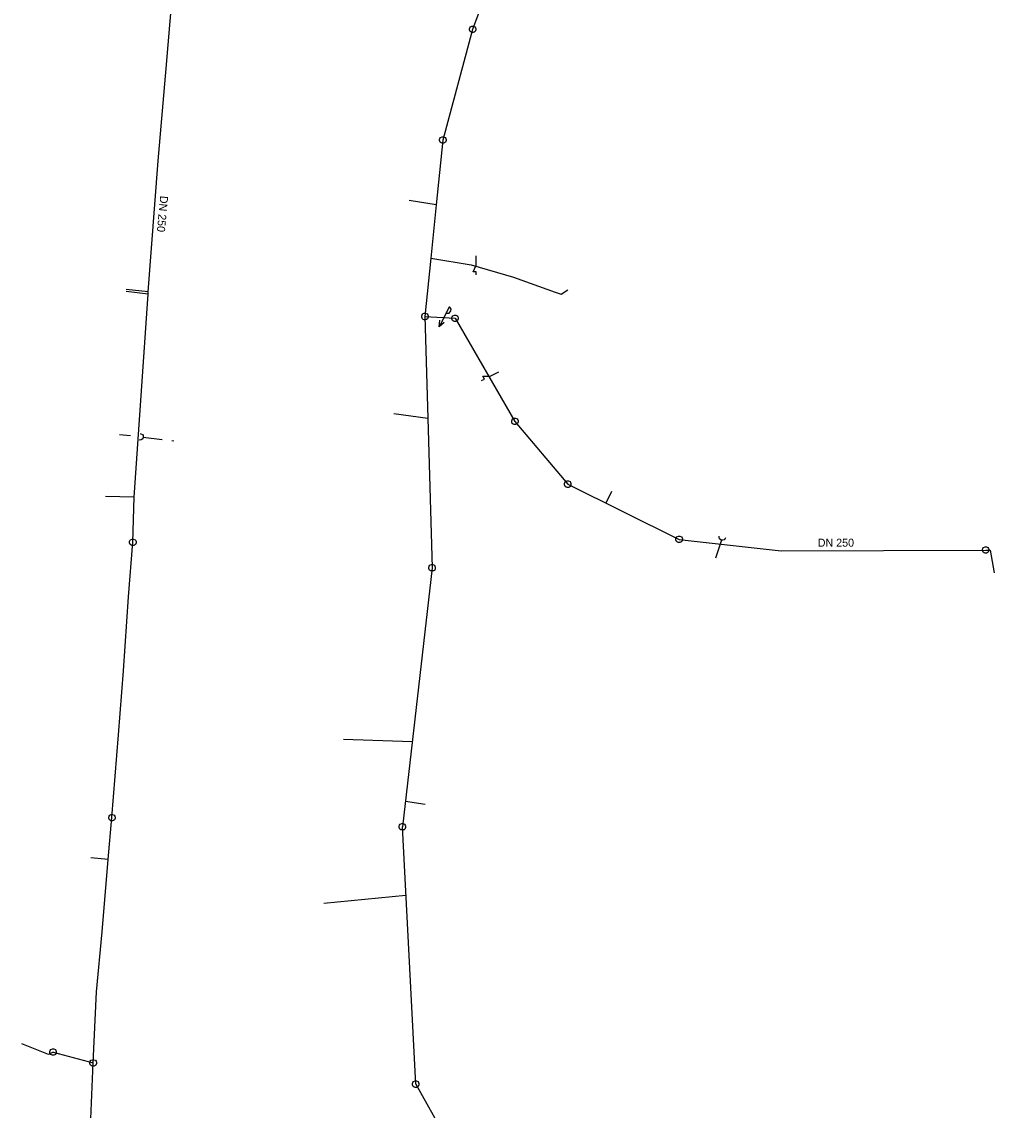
# Model space of a CAD drawing. Extents: x -717256 to -716843, y -1145423 to -1142840.
# Drawn here: x -716994.8 to -716842.9, y -1145075.9 to -1144905.8 of the extents above; entities that cross this region are included whole.
import ezdxf

# ---------------------------------------------------------------- set-up
doc = ezdxf.new("R2010")
doc.units = 0
for name, color, linetype in [('Vrstva 30', 7, 'Continuous'), ('Vrstva 31', 7, 'Continuous'), ('Vrstva 9', 7, 'Continuous')]:
    doc.layers.add(name, color=color, linetype=linetype)

msp = doc.modelspace()

# ---------------------------------------------------------------- linework, layer by layer
at = {"layer": 'Vrstva 30'}
for p, q in [((-716972.263, -1144913.081), (-716969.992, -1144886.715)), ((-716923.436, -1144904.319), (-716924.397, -1144906.971)), ((-716924.747, -1144906.571), (-716924.497, -1144906.471)), ((-716924.497, -1144906.471), (-716924.297, -1144906.471)), ((-716924.297, -1144906.471), (-716924.047, -1144906.571)), ((-716924.397, -1144906.971), (-716929.047, -1144924.264)), ((-716924.897, -1144906.871), (-716924.847, -1144906.721)), ((-716924.897, -1144907.071), (-716924.897, -1144906.871)), ((-716924.797, -1144907.321), (-716924.897, -1144907.071)), ((-716924.847, -1144906.721), (-716924.747, -1144906.571)), ((-716924.647, -1144907.421), (-716924.797, -1144907.321)), ((-716924.497, -1144907.471), (-716924.647, -1144907.421)), ((-716924.297, -1144907.471), (-716924.497, -1144907.471)), ((-716924.147, -1144907.421), (-716924.297, -1144907.471)), ((-716923.997, -1144907.321), (-716924.147, -1144907.421)), ((-716924.047, -1144906.571), (-716923.947, -1144906.721)), ((-716923.897, -1144907.071), (-716923.997, -1144907.321)), ((-716923.947, -1144906.721), (-716923.897, -1144906.871)), ((-716923.897, -1144906.871), (-716923.897, -1144907.071)), ((-716973.504, -1144927.52), (-716972.263, -1144913.081)), ((-716929.047, -1144924.264), (-716930.074, -1144934.378)), ((-716929.547, -1144924.164), (-716929.497, -1144924.014)), ((-716929.547, -1144924.364), (-716929.547, -1144924.164)), ((-716929.447, -1144924.614), (-716929.547, -1144924.364)), ((-716929.497, -1144924.014), (-716929.397, -1144923.864)), ((-716929.297, -1144924.714), (-716929.447, -1144924.614)), ((-716929.397, -1144923.864), (-716929.147, -1144923.764)), ((-716929.147, -1144924.764), (-716929.297, -1144924.714)), ((-716929.147, -1144923.764), (-716928.947, -1144923.764)), ((-716928.947, -1144924.764), (-716929.147, -1144924.764)), ((-716928.947, -1144923.764), (-716928.697, -1144923.864)), ((-716928.797, -1144924.714), (-716928.947, -1144924.764)), ((-716928.647, -1144924.614), (-716928.797, -1144924.714)), ((-716928.697, -1144923.864), (-716928.597, -1144924.014)), ((-716928.547, -1144924.364), (-716928.647, -1144924.614)), ((-716928.597, -1144924.014), (-716928.547, -1144924.164)), ((-716928.547, -1144924.164), (-716928.547, -1144924.364)), ((-716975.088, -1144947.993), (-716973.504, -1144927.52)), ((-716930.074, -1144934.378), (-716930.922, -1144942.731)), ((-716930.922, -1144942.731), (-716931.848, -1144951.843)), ((-716977.25, -1144980.08), (-716975.096, -1144948.367)), ((-716975.096, -1144948.367), (-716975.088, -1144947.993)), ((-716932.348, -1144951.743), (-716932.298, -1144951.593)), ((-716932.348, -1144951.943), (-716932.348, -1144951.743)), ((-716932.248, -1144952.193), (-716932.348, -1144951.943)), ((-716932.298, -1144951.593), (-716932.198, -1144951.443)), ((-716932.098, -1144952.293), (-716932.248, -1144952.193)), ((-716932.198, -1144951.443), (-716931.948, -1144951.343)), ((-716931.948, -1144952.343), (-716932.098, -1144952.293)), ((-716931.948, -1144951.343), (-716931.748, -1144951.343)), ((-716931.748, -1144952.343), (-716931.948, -1144952.343)), ((-716931.848, -1144951.843), (-716927.138, -1144952.119)), ((-716931.848, -1144951.843), (-716931.392, -1144967.726)), ((-716931.748, -1144951.343), (-716931.498, -1144951.443)), ((-716931.598, -1144952.293), (-716931.748, -1144952.343)), ((-716931.448, -1144952.193), (-716931.598, -1144952.293)), ((-716931.498, -1144951.443), (-716931.398, -1144951.593)), ((-716931.348, -1144951.943), (-716931.448, -1144952.193)), ((-716931.398, -1144951.593), (-716931.348, -1144951.743)), ((-716931.348, -1144951.743), (-716931.348, -1144951.943)), ((-716927.638, -1144952.019), (-716927.588, -1144951.869)), ((-716927.638, -1144952.219), (-716927.638, -1144952.019)), ((-716927.538, -1144952.469), (-716927.638, -1144952.219)), ((-716927.588, -1144951.869), (-716927.488, -1144951.719)), ((-716927.488, -1144951.719), (-716927.238, -1144951.619)), ((-716927.238, -1144951.619), (-716927.038, -1144951.619)), ((-716927.138, -1144952.119), (-716917.792, -1144968.219)), ((-716927.038, -1144951.619), (-716926.788, -1144951.719)), ((-716926.788, -1144951.719), (-716926.688, -1144951.869)), ((-716926.638, -1144952.219), (-716926.738, -1144952.469)), ((-716926.688, -1144951.869), (-716926.638, -1144952.019)), ((-716926.638, -1144952.019), (-716926.638, -1144952.219)), ((-716927.388, -1144952.569), (-716927.538, -1144952.469)), ((-716927.238, -1144952.619), (-716927.388, -1144952.569)), ((-716927.038, -1144952.619), (-716927.238, -1144952.619)), ((-716926.888, -1144952.569), (-716927.038, -1144952.619)), ((-716926.738, -1144952.469), (-716926.888, -1144952.569)), ((-716931.392, -1144967.726), (-716930.721, -1144991.101)), ((-716918.292, -1144968.119), (-716918.242, -1144967.969)), ((-716918.292, -1144968.319), (-716918.292, -1144968.119)), ((-716918.192, -1144968.569), (-716918.292, -1144968.319)), ((-716918.242, -1144967.969), (-716918.142, -1144967.819)), ((-716918.042, -1144968.669), (-716918.192, -1144968.569)), ((-716918.142, -1144967.819), (-716917.892, -1144967.719)), ((-716917.892, -1144968.719), (-716918.042, -1144968.669)), ((-716917.892, -1144967.719), (-716917.692, -1144967.719)), ((-716917.692, -1144968.719), (-716917.892, -1144968.719)), ((-716917.792, -1144968.219), (-716909.531, -1144978.04)), ((-716917.692, -1144967.719), (-716917.442, -1144967.819)), ((-716917.542, -1144968.669), (-716917.692, -1144968.719)), ((-716917.392, -1144968.569), (-716917.542, -1144968.669)), ((-716917.442, -1144967.819), (-716917.342, -1144967.969)), ((-716917.292, -1144968.319), (-716917.392, -1144968.569)), ((-716917.342, -1144967.969), (-716917.292, -1144968.119)), ((-716917.292, -1144968.119), (-716917.292, -1144968.319)), ((-716910.031, -1144977.94), (-716909.981, -1144977.79)), ((-716909.981, -1144977.79), (-716909.881, -1144977.64)), ((-716909.881, -1144977.64), (-716909.631, -1144977.54)), ((-716909.631, -1144977.54), (-716909.431, -1144977.54)), ((-716909.431, -1144977.54), (-716909.181, -1144977.64)), ((-716909.181, -1144977.64), (-716909.081, -1144977.79)), ((-716909.081, -1144977.79), (-716909.031, -1144977.94)), ((-716910.031, -1144978.14), (-716910.031, -1144977.94)), ((-716909.931, -1144978.39), (-716910.031, -1144978.14)), ((-716909.781, -1144978.49), (-716909.931, -1144978.39)), ((-716909.631, -1144978.54), (-716909.781, -1144978.49)), ((-716909.431, -1144978.54), (-716909.631, -1144978.54)), ((-716909.531, -1144978.04), (-716892.137, -1144986.656)), ((-716909.281, -1144978.49), (-716909.431, -1144978.54)), ((-716909.131, -1144978.39), (-716909.281, -1144978.49)), ((-716909.031, -1144978.14), (-716909.131, -1144978.39)), ((-716909.031, -1144977.94), (-716909.031, -1144978.14)), ((-716977.467, -1144987.107), (-716977.25, -1144980.08)), ((-716892.637, -1144986.556), (-716892.587, -1144986.406)), ((-716892.587, -1144986.406), (-716892.487, -1144986.256)), ((-716892.487, -1144986.256), (-716892.237, -1144986.156)), ((-716892.237, -1144986.156), (-716892.037, -1144986.156)), ((-716892.037, -1144986.156), (-716891.787, -1144986.256)), ((-716891.787, -1144986.256), (-716891.687, -1144986.406)), ((-716891.687, -1144986.406), (-716891.637, -1144986.556)), ((-716978.143, -1144995.62), (-716977.467, -1144987.107)), ((-716977.967, -1144987.007), (-716977.917, -1144986.857)), ((-716977.967, -1144987.207), (-716977.967, -1144987.007)), ((-716977.867, -1144987.457), (-716977.967, -1144987.207)), ((-716977.917, -1144986.857), (-716977.817, -1144986.707)), ((-716977.717, -1144987.557), (-716977.867, -1144987.457)), ((-716977.817, -1144986.707), (-716977.567, -1144986.607)), ((-716977.567, -1144987.607), (-716977.717, -1144987.557)), ((-716977.567, -1144986.607), (-716977.367, -1144986.607)), ((-716977.367, -1144987.607), (-716977.567, -1144987.607)), ((-716977.367, -1144986.607), (-716977.117, -1144986.707)), ((-716977.217, -1144987.557), (-716977.367, -1144987.607)), ((-716977.067, -1144987.457), (-716977.217, -1144987.557)), ((-716977.117, -1144986.707), (-716977.017, -1144986.857)), ((-716976.967, -1144987.207), (-716977.067, -1144987.457)), ((-716977.017, -1144986.857), (-716976.967, -1144987.007)), ((-716976.967, -1144987.007), (-716976.967, -1144987.207)), ((-716892.637, -1144986.756), (-716892.637, -1144986.556)), ((-716892.537, -1144987.006), (-716892.637, -1144986.756)), ((-716892.387, -1144987.106), (-716892.537, -1144987.006)), ((-716892.237, -1144987.156), (-716892.387, -1144987.106)), ((-716892.037, -1144987.156), (-716892.237, -1144987.156)), ((-716892.137, -1144986.656), (-716876.215, -1144988.451)), ((-716891.887, -1144987.106), (-716892.037, -1144987.156)), ((-716891.737, -1144987.006), (-716891.887, -1144987.106)), ((-716891.637, -1144986.756), (-716891.737, -1144987.006)), ((-716891.637, -1144986.556), (-716891.637, -1144986.756)), ((-716844.754, -1144988.229), (-716844.704, -1144988.079)), ((-716844.704, -1144988.079), (-716844.604, -1144987.929)), ((-716844.604, -1144987.929), (-716844.354, -1144987.829)), ((-716844.354, -1144987.829), (-716844.154, -1144987.829)), ((-716844.154, -1144987.829), (-716843.904, -1144987.929)), ((-716843.904, -1144987.929), (-716843.804, -1144988.079)), ((-716843.804, -1144988.079), (-716843.754, -1144988.229)), ((-716876.215, -1144988.451), (-716844.254, -1144988.329)), ((-716844.754, -1144988.429), (-716844.754, -1144988.229)), ((-716844.654, -1144988.679), (-716844.754, -1144988.429)), ((-716844.504, -1144988.779), (-716844.654, -1144988.679)), ((-716844.354, -1144988.829), (-716844.504, -1144988.779)), ((-716844.154, -1144988.829), (-716844.354, -1144988.829)), ((-716844.004, -1144988.779), (-716844.154, -1144988.829)), ((-716843.854, -1144988.679), (-716844.004, -1144988.779)), ((-716843.754, -1144988.429), (-716843.854, -1144988.679)), ((-716843.754, -1144988.229), (-716843.754, -1144988.429)), ((-716930.721, -1144991.101), (-716935.358, -1145031.568)), ((-716931.221, -1144991.001), (-716931.171, -1144990.851)), ((-716931.221, -1144991.201), (-716931.221, -1144991.001)), ((-716931.121, -1144991.451), (-716931.221, -1144991.201)), ((-716931.171, -1144990.851), (-716931.071, -1144990.701)), ((-716930.971, -1144991.551), (-716931.121, -1144991.451)), ((-716931.071, -1144990.701), (-716930.821, -1144990.601)), ((-716930.821, -1144990.601), (-716930.621, -1144990.601)), ((-716930.621, -1144990.601), (-716930.371, -1144990.701)), ((-716930.321, -1144991.451), (-716930.471, -1144991.551)), ((-716930.371, -1144990.701), (-716930.271, -1144990.851)), ((-716930.221, -1144991.201), (-716930.321, -1144991.451)), ((-716930.271, -1144990.851), (-716930.221, -1144991.001)), ((-716930.221, -1144991.001), (-716930.221, -1144991.201)), ((-716930.821, -1144991.601), (-716930.971, -1144991.551)), ((-716930.621, -1144991.601), (-716930.821, -1144991.601)), ((-716930.471, -1144991.551), (-716930.621, -1144991.601)), ((-716978.947, -1145007.212), (-716978.143, -1144995.62)), ((-716979.697, -1145017.216), (-716978.947, -1145007.212)), ((-716980.726, -1145030.141), (-716979.697, -1145017.216)), ((-716981.331, -1145036.665), (-716980.726, -1145030.141)), ((-716981.226, -1145030.041), (-716981.176, -1145029.891)), ((-716981.226, -1145030.241), (-716981.226, -1145030.041)), ((-716981.126, -1145030.491), (-716981.226, -1145030.241)), ((-716981.176, -1145029.891), (-716981.076, -1145029.741)), ((-716980.976, -1145030.591), (-716981.126, -1145030.491)), ((-716981.076, -1145029.741), (-716980.826, -1145029.641)), ((-716980.826, -1145030.641), (-716980.976, -1145030.591)), ((-716980.826, -1145029.641), (-716980.626, -1145029.641)), ((-716980.626, -1145029.641), (-716980.376, -1145029.741)), ((-716980.476, -1145030.591), (-716980.626, -1145030.641)), ((-716980.326, -1145030.491), (-716980.476, -1145030.591)), ((-716980.376, -1145029.741), (-716980.276, -1145029.891)), ((-716980.226, -1145030.241), (-716980.326, -1145030.491)), ((-716980.276, -1145029.891), (-716980.226, -1145030.041)), ((-716980.226, -1145030.041), (-716980.226, -1145030.241)), ((-716980.626, -1145030.641), (-716980.826, -1145030.641)), ((-716935.858, -1145031.468), (-716935.808, -1145031.318)), ((-716935.858, -1145031.668), (-716935.858, -1145031.468)), ((-716935.758, -1145031.918), (-716935.858, -1145031.668)), ((-716935.808, -1145031.318), (-716935.708, -1145031.168)), ((-716935.608, -1145032.018), (-716935.758, -1145031.918)), ((-716935.708, -1145031.168), (-716935.458, -1145031.068)), ((-716935.458, -1145032.068), (-716935.608, -1145032.018)), ((-716935.458, -1145031.068), (-716935.258, -1145031.068)), ((-716935.258, -1145032.068), (-716935.458, -1145032.068)), ((-716933.275, -1145071.777), (-716935.358, -1145031.568)), ((-716935.258, -1145031.068), (-716935.008, -1145031.168)), ((-716935.108, -1145032.018), (-716935.258, -1145032.068)), ((-716934.958, -1145031.918), (-716935.108, -1145032.018)), ((-716935.008, -1145031.168), (-716934.908, -1145031.318)), ((-716934.858, -1145031.668), (-716934.958, -1145031.918)), ((-716934.908, -1145031.318), (-716934.858, -1145031.468)), ((-716934.858, -1145031.468), (-716934.858, -1145031.668)), ((-716982.275, -1145047.99), (-716981.331, -1145036.665)), ((-716983.137, -1145057.338), (-716982.275, -1145047.99)), ((-716983.662, -1145068.455), (-716983.137, -1145057.338)), ((-716990.269, -1145066.37), (-716990.019, -1145066.27)), ((-716990.019, -1145066.27), (-716989.819, -1145066.27)), ((-716989.819, -1145066.27), (-716989.569, -1145066.37)), ((-716990.419, -1145066.67), (-716990.369, -1145066.52)), ((-716990.419, -1145066.87), (-716990.419, -1145066.67)), ((-716990.319, -1145067.12), (-716990.419, -1145066.87)), ((-716990.369, -1145066.52), (-716990.269, -1145066.37)), ((-716990.169, -1145067.22), (-716990.319, -1145067.12)), ((-716990.019, -1145067.27), (-716990.169, -1145067.22)), ((-716989.819, -1145067.27), (-716990.019, -1145067.27)), ((-716989.919, -1145066.77), (-716983.662, -1145068.455)), ((-716989.669, -1145067.22), (-716989.819, -1145067.27)), ((-716989.519, -1145067.12), (-716989.669, -1145067.22)), ((-716989.569, -1145066.37), (-716989.469, -1145066.52)), ((-716989.419, -1145066.87), (-716989.519, -1145067.12)), ((-716989.469, -1145066.52), (-716989.419, -1145066.67)), ((-716989.419, -1145066.67), (-716989.419, -1145066.87)), ((-716984.012, -1145068.055), (-716983.762, -1145067.955)), ((-716983.762, -1145067.955), (-716983.562, -1145067.955)), ((-716983.562, -1145067.955), (-716983.312, -1145068.055)), ((-716984.162, -1145068.355), (-716984.112, -1145068.205)), ((-716984.162, -1145068.555), (-716984.162, -1145068.355)), ((-716984.062, -1145068.805), (-716984.162, -1145068.555)), ((-716984.129, -1145079.722), (-716983.662, -1145068.455)), ((-716984.112, -1145068.205), (-716984.012, -1145068.055)), ((-716983.912, -1145068.905), (-716984.062, -1145068.805)), ((-716983.762, -1145068.955), (-716983.912, -1145068.905)), ((-716983.562, -1145068.955), (-716983.762, -1145068.955)), ((-716983.412, -1145068.905), (-716983.562, -1145068.955)), ((-716983.262, -1145068.805), (-716983.412, -1145068.905)), ((-716983.312, -1145068.055), (-716983.212, -1145068.205)), ((-716983.162, -1145068.555), (-716983.262, -1145068.805)), ((-716983.212, -1145068.205), (-716983.162, -1145068.355)), ((-716983.162, -1145068.355), (-716983.162, -1145068.555)), ((-716933.725, -1145071.527), (-716933.625, -1145071.377)), ((-716933.625, -1145071.377), (-716933.375, -1145071.277)), ((-716933.375, -1145071.277), (-716933.175, -1145071.277)), ((-716933.175, -1145071.277), (-716932.925, -1145071.377)), ((-716932.925, -1145071.377), (-716932.825, -1145071.527)), ((-716933.775, -1145071.677), (-716933.725, -1145071.527)), ((-716933.775, -1145071.877), (-716933.775, -1145071.677)), ((-716933.675, -1145072.127), (-716933.775, -1145071.877)), ((-716933.525, -1145072.227), (-716933.675, -1145072.127)), ((-716933.375, -1145072.277), (-716933.525, -1145072.227)), ((-716933.175, -1145072.277), (-716933.375, -1145072.277)), ((-716933.275, -1145071.777), (-716911.184, -1145111.128)), ((-716933.025, -1145072.227), (-716933.175, -1145072.277)), ((-716932.875, -1145072.127), (-716933.025, -1145072.227)), ((-716932.775, -1145071.877), (-716932.875, -1145072.127)), ((-716932.825, -1145071.527), (-716932.775, -1145071.677)), ((-716932.775, -1145071.677), (-716932.775, -1145071.877))]:
    msp.add_line(p, q, dxfattribs=at)
at = {"layer": 'Vrstva 31'}
for p, q in [((-716930.074, -1144934.378), (-716934.299, -1144933.737)), ((-716930.922, -1144942.731), (-716924.642, -1144943.776)), ((-716924.642, -1144943.776), (-716917.989, -1144945.692)), ((-716917.989, -1144945.692), (-716911.505, -1144948.049)), ((-716975.096, -1144948.367), (-716978.52, -1144947.931)), ((-716975.088, -1144947.993), (-716978.496, -1144947.594)), ((-716911.505, -1144948.049), (-716910.588, -1144948.348)), ((-716910.588, -1144948.348), (-716909.506, -1144947.682)), ((-716936.71, -1144967.003), (-716931.392, -1144967.726)), ((-716902.687, -1144979.2), (-716903.581, -1144980.986)), ((-716977.25, -1144980.08), (-716981.75, -1144979.943)), ((-716844.254, -1144988.329), (-716843.572, -1144988.333)), ((-716843.572, -1144988.333), (-716842.925, -1144991.884)), ((-716944.587, -1145017.897), (-716933.831, -1145018.249)), ((-716934.899, -1145027.564), (-716931.784, -1145028.011)), ((-716981.331, -1145036.665), (-716984.019, -1145036.428)), ((-716934.802, -1145042.292), (-716947.652, -1145043.568)), ((-716990.627, -1145067.143), (-716994.811, -1145065.479)), ((-716989.919, -1145066.77), (-716990.627, -1145067.143))]:
    msp.add_line(p, q, dxfattribs=at)
at = {"layer": 'Vrstva 9'}
for p, q in [((-716924.323, -1144944.837), (-716923.823, -1144943.837)), ((-716923.823, -1144943.837), (-716923.823, -1144942.337)), ((-716923.823, -1144944.837), (-716924.323, -1144944.837)), ((-716923.823, -1144945.337), (-716923.823, -1144944.837)), ((-716928.049, -1144950.355), (-716929.638, -1144953.474)), ((-716927.96, -1144950.401), (-716928.049, -1144950.355)), ((-716927.849, -1144950.513), (-716927.96, -1144950.401)), ((-716927.761, -1144950.67), (-716927.849, -1144950.513)), ((-716927.785, -1144950.939), (-716927.761, -1144950.67)), ((-716929.638, -1144953.474), (-716929.54, -1144952.401)), ((-716928.503, -1144951.246), (-716928.414, -1144951.292)), ((-716928.414, -1144951.292), (-716928.258, -1144951.315)), ((-716928.258, -1144951.315), (-716928.079, -1144951.294)), ((-716928.079, -1144951.294), (-716927.876, -1144951.117)), ((-716927.876, -1144951.117), (-716927.785, -1144950.939)), ((-716928.828, -1144952.764), (-716929.638, -1144953.474)), ((-716921.658, -1144961.16), (-716920.321, -1144960.479)), ((-716922.994, -1144961.84), (-716922.549, -1144961.614)), ((-716922.776, -1144961.168), (-716921.658, -1144961.16)), ((-716922.549, -1144961.614), (-716922.776, -1144961.168)), ((-716979.548, -1144970.257), (-716977.842, -1144970.456)), ((-716976.157, -1144971.106), (-716976.311, -1144971.138)), ((-716976.295, -1144970.133), (-716976.195, -1144970.145)), ((-716976.195, -1144970.145), (-716975.959, -1144970.273)), ((-716975.996, -1144971.024), (-716976.157, -1144971.106)), ((-716975.868, -1144970.787), (-716975.996, -1144971.024)), ((-716975.959, -1144970.273), (-716975.877, -1144970.434)), ((-716975.877, -1144970.434), (-716975.844, -1144970.588)), ((-716975.844, -1144970.588), (-716975.868, -1144970.787)), ((-716975.856, -1144970.688), (-716972.876, -1144971.036)), ((-716976.311, -1144971.138), (-716976.411, -1144971.126)), ((-716971.386, -1144971.21), (-716971.065, -1144971.248)), ((-716885.894, -1144986.23), (-716885.863, -1144986.135)), ((-716885.893, -1144986.388), (-716885.894, -1144986.23)), ((-716885.844, -1144986.561), (-716885.893, -1144986.388)), ((-716885.542, -1144986.765), (-716886.469, -1144989.618)), ((-716885.637, -1144986.734), (-716885.844, -1144986.561)), ((-716885.447, -1144986.796), (-716885.637, -1144986.734)), ((-716885.289, -1144986.794), (-716885.447, -1144986.796)), ((-716885.115, -1144986.746), (-716885.289, -1144986.794)), ((-716884.943, -1144986.539), (-716885.115, -1144986.746)), ((-716884.912, -1144986.444), (-716884.943, -1144986.539))]:
    msp.add_line(p, q, dxfattribs=at)

# ---------------------------------------------------------------- texts
at = {"layer": 'Vrstva 30'}
msp.add_text('DN 250', height=1.25, rotation=264.6, dxfattribs=at).set_placement((-716973.181, -1144932.937))
msp.add_text('DN 250', height=1.25, dxfattribs=at).set_placement((-716870.49, -1144987.804))

doc.saveas('drawing.dxf')
